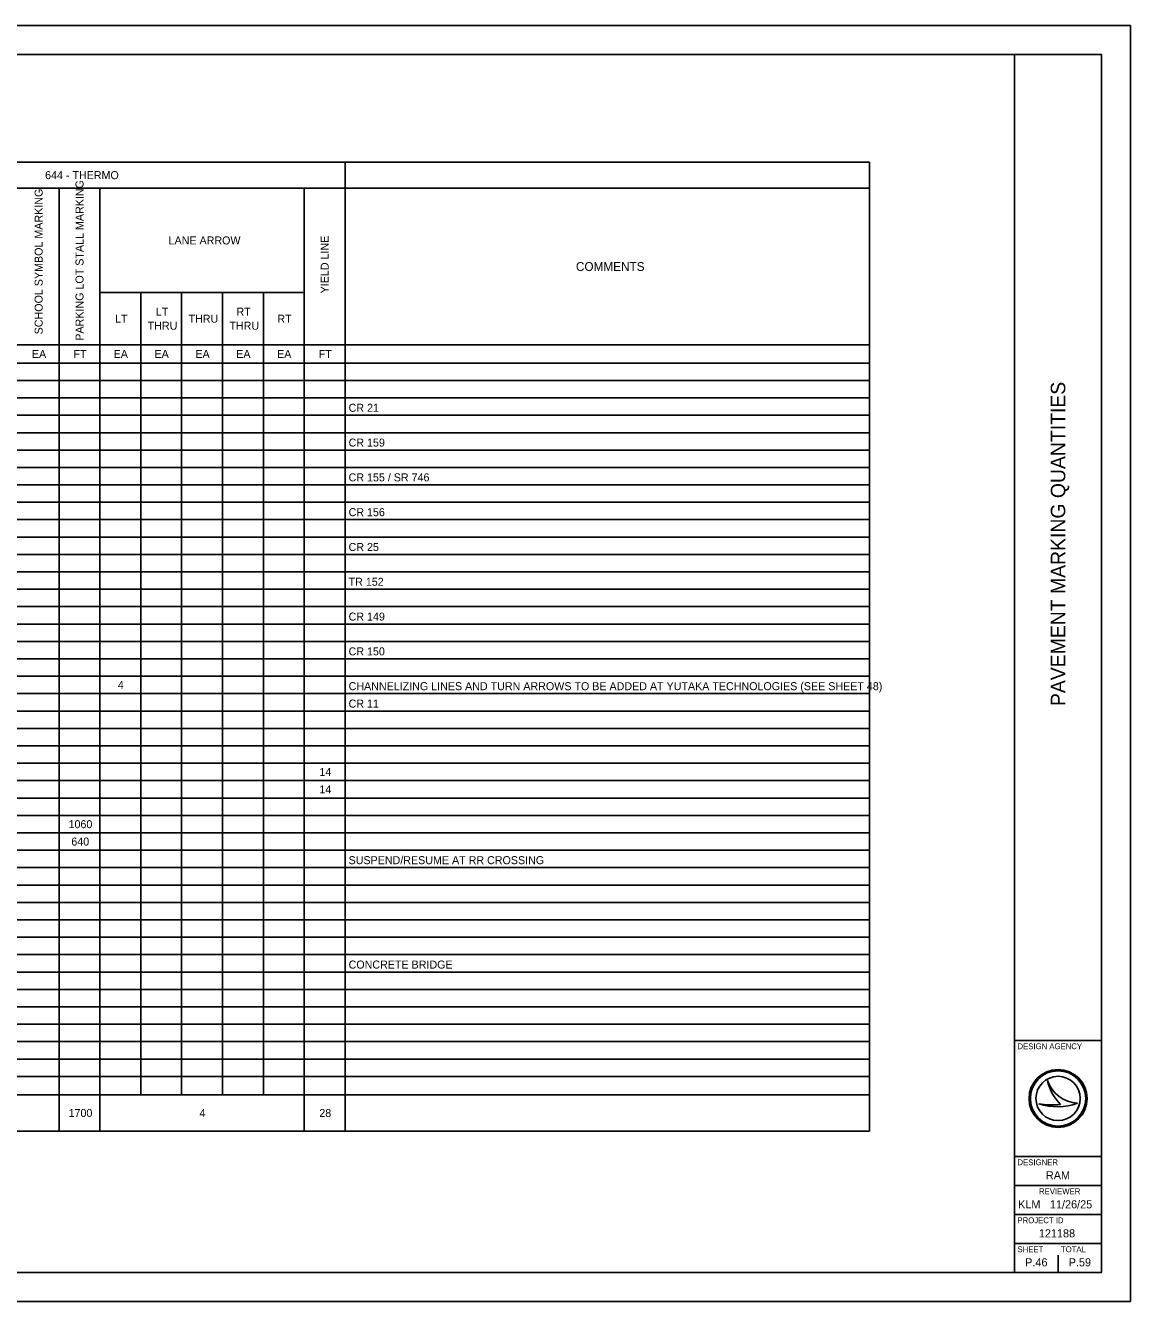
# Model space of a CAD drawing. Extents: x 0 to 34, y 0 to 22.
# Drawn here: x 14.94 to 34, y 0 to 22 of the extents above; entities that cross this region are included whole.
import ezdxf

# ---------------------------------------------------------------- set-up
doc = ezdxf.new("R2010")
doc.units = 0
for name, color, linetype in [('Default', 7, 'Continuous'), ('SH_Border', 7, 'Continuous'), ('SH_Cut_Line', 7, 'Continuous'), ('SH_Data', 7, 'Continuous')]:
    doc.layers.add(name, color=color, linetype=linetype)

msp = doc.modelspace()

# ---------------------------------------------------------------- linework, layer by layer
at = {"layer": 'Default'}
for p, q in [((9.171, 19.645), (29.496, 19.645)), ((20.451, 19.645), (20.451, 2.935)), ((29.496, 19.645), (29.496, 2.935)), ((2.181, 19.195), (29.496, 19.195)), ((15.516, 19.195), (15.516, 2.935)), ((16.221, 19.195), (16.221, 2.935)), ((19.746, 19.195), (19.746, 2.935)), ((16.221, 17.395), (19.746, 17.395)), ((16.926, 17.395), (16.926, 3.565)), ((17.631, 17.395), (17.631, 3.565)), ((18.336, 17.395), (18.336, 3.565)), ((19.041, 17.395), (19.041, 3.565)), ((7.896, 16.495), (29.496, 16.495)), ((2.181, 16.18), (29.496, 16.18)), ((2.181, 15.88), (29.496, 15.88)), ((3.216, 15.58), (29.496, 15.58)), ((3.216, 15.28), (29.496, 15.28)), ((3.216, 14.98), (29.496, 14.98)), ((3.216, 14.68), (29.496, 14.68)), ((3.216, 14.38), (29.496, 14.38)), ((3.216, 14.08), (29.496, 14.08)), ((3.216, 13.78), (29.496, 13.78)), ((3.216, 13.48), (29.496, 13.48)), ((3.216, 13.18), (29.496, 13.18)), ((3.216, 12.88), (29.496, 12.88)), ((3.216, 12.58), (29.496, 12.58)), ((3.216, 12.28), (29.496, 12.28)), ((3.216, 11.98), (29.496, 11.98)), ((3.216, 11.68), (29.496, 11.68)), ((3.216, 11.38), (29.496, 11.38)), ((3.216, 11.08), (29.496, 11.08)), ((3.216, 10.78), (29.496, 10.78)), ((3.216, 10.48), (29.496, 10.48)), ((3.216, 10.18), (29.496, 10.18)), ((2.181, 9.88), (29.496, 9.88)), ((2.181, 9.58), (29.496, 9.58)), ((2.181, 9.28), (29.496, 9.28)), ((2.181, 8.98), (29.496, 8.98)), ((2.181, 8.68), (29.496, 8.68)), ((2.181, 8.38), (29.496, 8.38)), ((2.181, 8.08), (29.496, 8.08)), ((2.181, 7.78), (29.496, 7.78)), ((2.181, 7.48), (29.496, 7.48)), ((2.181, 7.18), (29.496, 7.18)), ((2.181, 6.88), (29.496, 6.88)), ((2.181, 6.58), (29.496, 6.58)), ((2.181, 6.28), (29.496, 6.28)), ((2.181, 5.98), (29.496, 5.98)), ((2.181, 5.68), (29.496, 5.68)), ((2.181, 5.38), (29.496, 5.38)), ((2.181, 5.08), (29.496, 5.08)), ((2.181, 4.78), (29.496, 4.78)), ((2.181, 4.48), (29.496, 4.48)), ((2.181, 4.18), (29.496, 4.18)), ((2.181, 3.88), (29.496, 3.88)), ((2.181, 3.565), (29.496, 3.565)), ((3.216, 2.935), (29.496, 2.935))]:
    msp.add_line(p, q, dxfattribs=at)
for points in [[(15.516, 8.38), (16.221, 8.38), (16.221, 8.08), (15.516, 8.08)], [(15.516, 8.08), (16.221, 8.08), (16.221, 7.78), (15.516, 7.78)]]:
    msp.add_lwpolyline(points, close=True, dxfattribs=at)
at = {"layer": 'SH_Border'}
for p, q in [((32, 0.5), (32, 21.5)), ((32, 4.5), (33.5, 4.5)), ((32, 2.5), (33.5, 2.5)), ((32, 2), (33.5, 2)), ((32, 1.5), (33.5, 1.5)), ((32, 1), (33.5, 1))]:
    msp.add_line(p, q, dxfattribs=at)
msp.add_lwpolyline([(1.5, 21.5), (33.5, 21.5), (33.5, 0.5), (1.5, 0.5)], close=True, dxfattribs=at)
at = {"layer": 'SH_Cut_Line'}
msp.add_lwpolyline([(0, 0), (34, 0), (34, 22), (0, 22)], close=True, dxfattribs=at)
at = {"layer": 'SH_Data'}
for p, q in [((32.567, 3.81), (32.567, 3.81)), ((32.417, 3.41), (32.417, 3.41)), ((32.75, 3.5), (32.75, 3.5)), ((33.087, 3.419), (33.087, 3.419)), ((32.375, 0.675), (32.375, 0.675)), ((32.75, 0.5), (32.75, 0.8))]:
    msp.add_line(p, q, dxfattribs=at)
for radius in [0.5, 0.477, 0.477, 0.382]:
    msp.add_circle((32.75, 3.5), radius, dxfattribs=at)
for centre, radius, start, end in [((33.116, 3.998), 0.58, 198.9257, 198.9319), ((33.347, 3.97), 0.796, 191.6379, 191.6421), ((33.116, 3.998), 0.58, 198.9319, 267.1657), ((33.347, 3.97), 0.796, 191.6421, 226.0947), ((32.739, 4.37), 1.013, 251.4576, 290.0832), ((32.648, 4.654), 1.266, 259.4964, 259.4995), ((32.739, 4.37), 1.013, 251.4527, 251.4576), ((32.648, 4.654), 1.266, 259.4995, 276.6672)]:
    msp.add_arc(centre, radius, start, end, dxfattribs=at)

# ---------------------------------------------------------------- texts
at = {"layer": 'Default'}
for s, height, p in [('644 - THERMO', 0.138, (15.275, 19.351)), ('LANE ARROW', 0.138, (17.406, 18.226)), ('COMMENTS', 0.1518, (24.433, 17.769)), ('LT', 0.138, (16.481, 16.876)), ('LT ', 0.138, (17.186, 16.997)), ('THRU', 0.138, (17.75, 16.876)), ('RT ', 0.138, (18.577, 16.997)), ('RT', 0.138, (19.282, 16.876)), ('THRU', 0.138, (17.045, 16.755)), ('THRU', 0.138, (18.455, 16.755)), ('EA', 0.138, (15.048, 16.268)), ('FT', 0.138, (15.765, 16.268)), ('EA', 0.138, (16.458, 16.268)), ('EA', 0.138, (17.163, 16.268)), ('EA', 0.138, (17.868, 16.268)), ('EA', 0.138, (18.573, 16.268)), ('EA', 0.138, (19.278, 16.268)), ('FT', 0.138, (19.995, 16.268)), ('CR 21', 0.138, (20.511, 15.34)), ('CR 159', 0.138, (20.511, 14.74)), ('CR 155 / SR 746', 0.138, (20.511, 14.14)), ('CR 156', 0.138, (20.511, 13.54)), ('CR 25', 0.138, (20.511, 12.94)), ('TR 152', 0.138, (20.511, 12.34)), ('CR 149', 0.138, (20.511, 11.74)), ('CR 150', 0.138, (20.511, 11.14)), ('4', 0.138, (16.53, 10.561)), ('CHANNELIZING LINES AND TURN ARROWS TO BE ADDED AT YUTAKA TECHNOLOGIES (SEE SHEET 48)', 0.138, (20.511, 10.54)), ('CR 11', 0.138, (20.511, 10.24)), ('14', 0.138, (20.007, 9.061)), ('14', 0.138, (20.007, 8.761)), ('1060', 0.138, (15.68, 8.161)), ('640', 0.138, (15.728, 7.861)), ('SUSPEND/RESUME AT RR CROSSING', 0.138, (20.511, 7.54)), ('CONCRETE BRIDGE', 0.138, (20.511, 5.74)), ('1700', 0.138, (15.68, 3.181)), ('4', 0.138, (17.94, 3.181)), ('28', 0.138, (20.006, 3.181))]:
    msp.add_text(s, height=height, dxfattribs=at).set_placement(p)
for s, p in [('SCHOOL SYMBOL MARKING', (15.233, 16.675)), ('PARKING LOT STALL MARKING', (15.938, 16.566)), ('YIELD LINE', (20.168, 17.382))]:
    msp.add_text(s, height=0.138, rotation=90, dxfattribs=at).set_placement(p)
at = {"layer": 'SH_Data'}
msp.add_text('PAVEMENT MARKING QUANTITIES', height=0.25, rotation=90, dxfattribs=at).set_placement((32.875, 10.266))
for s, height, p in [('DESIGN AGENCY', 0.1, (32.05, 4.35)), ('DESIGNER', 0.1, (32.05, 2.35)), ('RAM', 0.14, (32.541, 2.105)), ('REVIEWER', 0.1, (32.422, 1.85)), ('KLM', 0.14, (32.061, 1.605)), ('11/26/25', 0.14, (32.611, 1.605)), ('PROJECT ID', 0.1, (32.05, 1.35)), ('121188', 0.14, (32.419, 1.105)), ('SHEET', 0.1, (32.05, 0.85)), ('TOTAL', 0.1, (32.8, 0.85)), ('P.46', 0.14, (32.183, 0.605)), ('P.59', 0.14, (32.934, 0.605))]:
    msp.add_text(s, height=height, dxfattribs=at).set_placement(p)

doc.saveas('drawing.dxf')
